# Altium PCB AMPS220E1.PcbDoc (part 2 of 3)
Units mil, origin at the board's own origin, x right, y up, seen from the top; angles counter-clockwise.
Board outline 4800 x 2800 mil, 4 copper layers (Top Layer, GND_Split, GROUND, Bottom Layer), stack 62.6 mil thick; 263 components, 127 nets, 663 pads, 225 vias.
Unrouted connection lines stored in the file: 38.
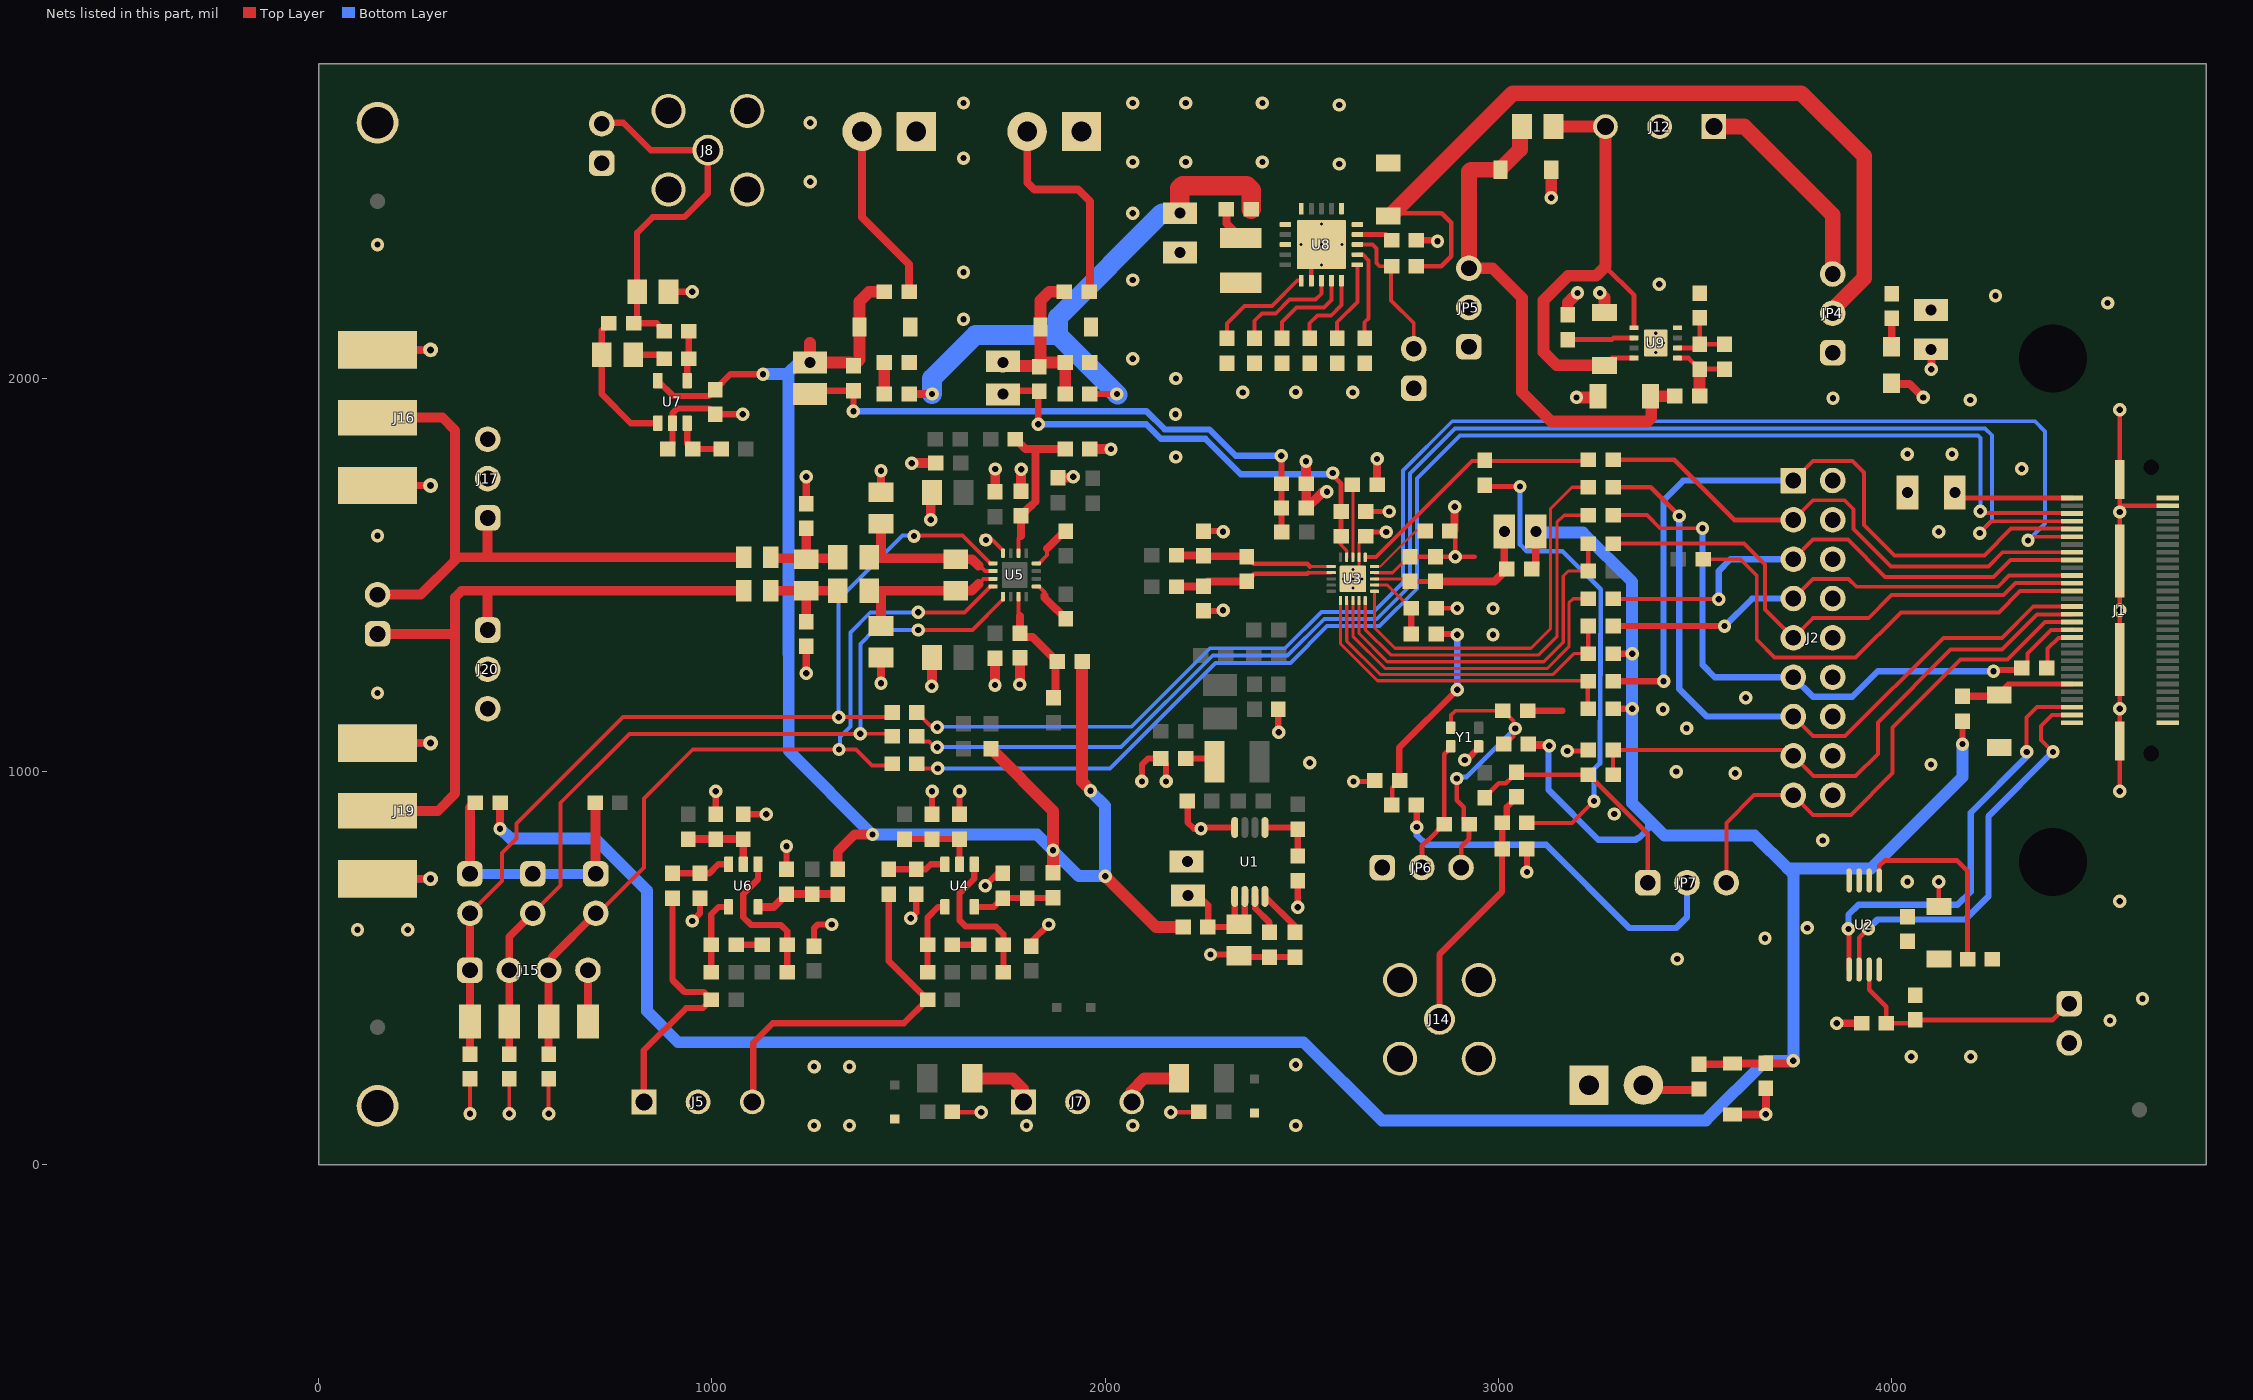
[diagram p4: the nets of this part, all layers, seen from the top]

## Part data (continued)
J3 J4 J6 J18 JP1 JP2: library part CMP-0075405-3, "Header, 100mil, 2x1, Gold, TH", Color=Black, Current_A=6.3A, Manufacturer=Samtec, PartNumber=TSW-102-07-G-S, Supplier Part Number 1=SAM1029-02-ND, Voltage_V=550V
J5 J7 J12: library part CMP-0055340-2, "Terminal Block, 3.5 mm, 3x1, Tin, TH", Manufacturer=Molex, Supplier Part Number 1=WM7878-ND
J8 J14: library part CMP-0055833-1, "SMA Straight Jack, Gold, 50 Ohm, TH", Manufacturer="Amphenol RF", Supplier Part Number 1=ARFX1231-ND
J9: library part CMP-0075405-3, "Header, 100mil, 2x1, Gold, TH", Color=Black, Current_A=6.3A, Manufacturer=Samtec, Supplier Part Number 1=SAM1029-02-ND, Voltage_V=550V
J10 J11 J13: library part CMP-0074913-1, "Terminal Block, 3.5mm Pitch, 2x1, TH", Color=Grey, Current_A=6A, Manufacturer="On-Shore Technology", Supplier Part Number 1=ED1514-ND, Voltage_V=150V
J15: library part CMP-0075409-2, "Header, 100mil, 4x1, Gold, TH", Color=Black, Current_A=6.3A, Manufacturer=Samtec, Supplier Part Number 1=SAM1029-04-ND, Voltage_V=550V
J16 J19: library part CMP-0055828-1, "Connector, End launch SMA, 50 ohm, SMT", Manufacturer="Cinch Connectivity", Supplier Part Number 1=J502-ND
J17 J20 JP4 JP5 JP6 JP7: library part CMP-0075407-2, "Header, 100mil, 3x1, Gold, TH", Color=Black, Current_A=6.3A, Manufacturer=Samtec, Supplier Part Number 1=SAM1029-03-ND, Voltage_V=550V
LBL1: library part CMP-0003625-1, "Thermal Transfer Printable Labels, 0.650\" W x 0.200\" H - 10,000 per roll", Manufacturer=Brady, Supplier Part Number 1=97C5133
Logo1: library part CMP-0074844-1
Logo2: library part CMP-0074769-1
Logo3: library part CMP-0074838-1, "Texas Instrument Corporate Signature"
Logo4: library part CMP-0074847-1, "FCC_disclaimer"
R1 R2 R4 R17 R21 R22 R23 R29 R30 R33 R35 R37 R41 R42 R45 R50 R51 R52 R53 R54 R56 R57 R59 R60 R71 R72 R73 R74 R75 R78 R81 R82 R83 R84 R89 R90 R92 R93 R94 R96 R97 R98 R100 R101 R196 R197: library part CMP-0025885-5, "RES, 0, 5%, 0.1 W, 0603", Manufacturer=Yageo, Power_W=100mW, Supplier Part Number 1=311-0.0GRCT-ND, TempCo="200 ppm/C", Tolerance_%=5%, Value2=0.1W, Value_Code=0000, ValueDisplayed=0
R3 R65 R70 R86: library part CMP-0022746-5, "RES, 10.0 k, 1%, 0.1 W, 0603", Manufacturer=Yageo, Power_W=100mW, Supplier Part Number 1=311-10.0KHRCT-ND, TempCo="100 ppm/C", Tolerance_%=1%, Value2=0.1W, Value_Code=10k0, ValueDisplayed=10.0k
R5: library part CMP-0022726-3, "RES, 0.047, 1%, 0.1 W, AEC-Q200 Grade 1, 0603", Manufacturer=Panasonic, Power_W=100mW, Supplier Part Number 1=P47LJCT-ND, TempCo="200 ppm/C", Tolerance_%=1%, Value2=0.1W, Value_Code=R047, ValueDisplayed=0.047
R6: library part CMP-0023427-3, "RES, 120 k, 0.1%, 0.1 W, 0603", Manufacturer="Susumu Co Ltd", Power_W=100mW, Supplier Part Number 1=RG16P120KBCT-ND, TempCo="25 ppm/C", Tolerance_%=0.1%, Value2=0.1W, Value_Code=120k
R7 R11 R15 R69: library part CMP-0022725-3, "RES, 0.1, 1%, 0.1 W, AEC-Q200 Grade 1, 0603", Manufacturer=Panasonic, Power_W=100mW, Supplier Part Number 1=P100LJCT-ND, TempCo="200 ppm/C", Tolerance_%=1%, Value2=0.1W, Value_Code=R100, ValueDisplayed=0.1
R8 R9 R10 R12 R13 R14 R16 R18 R32 R47 R67 R95 R129 R130: library part CMP-0022004-4, "RES, 10.0, 1%, 0.25 W, AEC-Q200 Grade 0, 0603", Manufacturer=Vishay-Dale, Power_W=250mW, Supplier Part Number 1=541-10.0SCT-ND, TempCo="100 ppm/C", Tolerance_%=1%, Value2=0.25W, Value_Code=10R0, ValueDisplayed=10.0
R19 R20 R68 R91 R198: library part CMP-0021990-4, "RES, 100 k, 1%, 0.1 W, AEC-Q200 Grade 0, 0603", Manufacturer=Vishay-Dale, Power_W=100mW, Supplier Part Number 1=541-100KHCT-ND, TempCo="100 ppm/C", Tolerance_%=1%, Value2=0.1W, Value_Code=100k
R24 R31 R36 R46 R58 R63 R66: library part CMP-0022109-5, "RES, 1.00 k, 1%, 0.1 W, AEC-Q200 Grade 0, 0603", Manufacturer=Vishay-Dale, Power_W=100mW, Supplier Part Number 1=541-1.00KHCT-ND, TempCo="100 ppm/C", Tolerance_%=1%, Value2=0.1W, Value_Code=1k00, ValueDisplayed=1.00k
R25 R34 R49 R55: library part CMP-0021991-4, "RES, 100, 1%, 0.1 W, AEC-Q200 Grade 0, 0603", Manufacturer=Vishay-Dale, Power_W=100mW, Supplier Part Number 1=541-100HCT-ND, TempCo="100 ppm/C", Tolerance_%=1%, Value2=0.1W, Value_Code=100R, ValueDisplayed=100
R26 R27 R28: library part CMP-0023337-3, "RES, 10.0 k, 1%, 0.1 W, 0603", Manufacturer="Vishay Draloric", Power_W=100mW, Supplier Part Number 1=541-1784-1-ND, TempCo="100 ppm/C", Tolerance_%=1%, Value2=0.1W, Value_Code=10k0, ValueDisplayed=10.0k
R38 R44: library part CMP-0024268-3, "RES, 47.5, 0.1%, 0.1 W, 0603", Manufacturer="Yageo America", Power_W=100mW, TempCo="25 ppm/C", Tolerance_%=0.1%, Value2=0.1W, Value_Code=47R5, ValueDisplayed=47.5
R39 R48: library part CMP-0020833-2, "RES, 0, 1%, 0.5 W, 0805", Manufacturer=Keystone, Power_W=500mW, Supplier Part Number 1=36-5106CT-ND, TempCo=ppm/C, Tolerance_%=1%, Value2=0.5W, Value_Code=0
R40 R43: library part CMP-0018851-2, "RES, 100, 0.1%, 0.125 W, 0805", Manufacturer="Susumu Co Ltd", Power_W=125mW, Supplier Part Number 1=RG20P100BCT-ND, TempCo="25 ppm/C", Tolerance_%=0.1%, Value2=0.125W, Value_Code=100R, ValueDisplayed=100
R61 R62: library part CMP-0018402-2, "RES, 5.49, 1%, 0.25 W, 1206", Manufacturer="Yageo America", Power_W=250mW, Supplier Part Number 1=311-5.49FRCT-ND, TempCo="200 ppm/C", Tolerance_%=1%, Value2=0.25W, Value_Code=5R49, ValueDisplayed=5.49
R64: library part CMP-0023063-4, "RES, 37.4, 1%, 0.1 W, 0603", Manufacturer=Yageo, Power_W=100mW, Supplier Part Number 1=311-37.4HRCT-ND, TempCo="100 ppm/C", Tolerance_%=1%, Value2=0.1W, Value_Code=37R4, ValueDisplayed=37.4
R76 R77 R79: library part CMP-0023206-5, "RES, 5.11, 1%, 0.1 W, 0603", Manufacturer=Yageo, Power_W=100mW, Supplier Part Number 1=311-5.11HRCT-ND, TempCo="200 ppm/C", Tolerance_%=1%, Value2=0.1W, Value_Code=5R11, ValueDisplayed=5.11
R80: library part CMP-0022760-5, "RES, 11.3 k, 1%, 0.1 W, 0603", Manufacturer=Yageo, Power_W=100mW, Supplier Part Number 1=311-11.3KHRCT-ND, TempCo="100 ppm/C", Tolerance_%=1%, Value2=0.1W, Value_Code=11k3, ValueDisplayed=11.3k
R85: library part CMP-0020803-2, "RES, 0, 5%, 0.125 W, 0805", Manufacturer="Yageo America", Power_W=125mW, Supplier Part Number 1=311-0.0ARCT-ND, TempCo="200 ppm/C", Tolerance_%=5%, Value2=0.125W, Value_Code=0000, ValueDisplayed=0
R87 R88: library part CMP-0024285-2, "RES, 49.9, 0.1%, 0.1 W, 0603", Manufacturer="Yageo America", Power_W=100mW, TempCo="25 ppm/C", Tolerance_%=0.1%, Value2=0.1W, Value_Code=49R9, ValueDisplayed=49.9
SH-J1 SH-J2 SH-J3 SH-J4 SH-J5 SH-J6 SH-J7 SH-J8 SH-J9: library part CMP-0003642-1, "Shunt, 100mil, Flash Gold, Black", Manufacturer="Sullins Connector Solutions", Supplier Part Number 1=S9001-ND
TP1 TP2 TP3 TP4 TP5 TP6 TP7 TP8 TP9 TP10 TP11 TP12 TP13 TP14 TP15 TP16 TP19 TP20 TP21 TP22: library part CMP-0003968-1, "Test Point, SMT", Manufacturer=Harwin, PartNumber=S2751-46R, Supplier Part Number 1=952-2664-1-ND
TP17 TP18: library part CMP-0055119-1, "Terminal, Turret, TH, Double", Manufacturer=Keystone, PartNumber=1573-2, Supplier Part Number 1=36-1573-2-ND
U1: library part CMP-0077708-1, "High-Precision Voltage Reference with Integrated High-Bandwidth Buffer, DGK0008A (VSSOP-8)", Alternate Manufacturer="Texas Instruments", Alternate PartNumber=REF6225IDGKT
U2: library part CMP-0004843-1, "I2C BUS EEPROM (2-Wire), TSSOP-B8", Manufacturer=Rohm, Supplier Part Number 1=BR24G32FVT-3AG2CT-ND
U3: library part CMP-0097348-1, "512-kSPS, Wide-Bandwidth, 24-Bit, Delta-Sigma ADC", Manufacturer="Texas Instruments", Max Supply Voltage=5.5V, Min Supply Voltage=1.65V, Operating Temperature Range="to +150°C"
U4 U6 U7: library part CMP-0040538-1, "Precision, Rail-to-Rail Input/Output, Low Offset Voltage, Low Input Bias Current Op Amp with E-trim, 4.5 to 36 V, -40 to 125 degC, 5-Pin SOT-23 (DBV), Green (RoHS & no Sb/Br), Tape and Reel", Temperature Max="125 degC", Temperature Min="-40 degC"
U5: library part CMP-0120091-1, "Low-Noise, Wide-Bandwidth, Fully Differential Output Programmable-Gain Instrumentation Amplifier", Input Bias Current=0.0005uA, Input Offset Voltage=0.07mV, Manufacturer="Texas Instruments", Max Dual Supply Voltage=18V, Max Supply Voltage=36V, Min Dual Supply Voltage=4V, Min Supply Voltage=8V, Nominal Supply Current=3mA, Operating Temperature Range="-40°C to +125°C", Output Current Per Channel=45mA, Voltage Gain=0.000125-0.016V/mV
U8: library part CMP-0066918-2, "36-V, 1-A, 4.17-uVRMS, RF LDO Voltage Regulator, RGW0020A (VQFN-20)", Alternate Manufacturer="Texas Instruments", Alternate PartNumber=TPS7A4700RGWT
U9: library part CMP-0073865-3, "Vin -3V to -36V, -200mA, Ultra-Low-Noise, High-PSRR, Low-Dropout (LDO) Linear Regulator, DRB0008A (VSON-8)", Alternate Manufacturer="Texas Instruments", Alternate PartNumber=TPS7A3001DRBT, Operating Temperature Range="-40 to 125 C", Rating=Catalog
Y1: library part CMP-0095447-1, "32.768 MHz XO (Standard) CMOS Oscillator 1.6V ~ 3.63V Standby (Power Down) 4-SMD, No Lead", Digikey Part Number=478-KC2016K32.7680C1GE00CT-ND, Frequency_Fixed=32.768MHz, Load Capacitance=15pF, Manufacturer=Kyocera, Max Supply Current=3.5-5mA, Max Supply Voltage=3.63V, Min Supply Voltage=1.6V, Mouser Part Number=581-KC2016K32.76C1GE, Operating Temperature Range="-40°C to +85°C"
ZZ1: library part CMP-0003616-3
ZZ2: library part CMP-0077236-1
ZZ3: library part CMP-0077237-1
ZZ4: library part CMP-0077238-1

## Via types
v1: diameter 34, hole 16, Top Layer to Bottom Layer, tented both sides, 161 vias
v2: diameter 34, hole 16, Top Layer to Bottom Layer, 30 vias
v3: diameter 50, hole 28, Top Layer to Bottom Layer, 15 vias
v4: diameter 19.68, hole 7.87, Top Layer to Bottom Layer, tented both sides, 10 vias
v5: diameter 19.68, hole 7.87, Top Layer to Bottom Layer, 9 vias

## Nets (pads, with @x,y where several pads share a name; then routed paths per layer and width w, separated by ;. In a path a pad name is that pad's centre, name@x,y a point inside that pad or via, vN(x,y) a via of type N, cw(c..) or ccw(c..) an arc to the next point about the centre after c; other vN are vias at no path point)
5V_LDO: R69.2 R71.2 R74.2 TP14.1 U8.1 U8.3 U8.20 | length 1501
  Top Layer w16: R74.2@1961.5,1960 v1(2030,1960)
  Top Layer w20: R71.2@1501.5,1960 v1@1548.5,1960
  Top Layer w50: v3(2190,2420) 2190,2482.95 2197.05,2490 2359.61,2490 2371.5,2478.11 R69.2@2371.5,2430
  Bottom Layer w50: v1(1560,1960) 1560,1999.47 1670.53,2110 1880,2110 ; v1@2032.05,1957.95 v1(2030,1960) 1880,2110 ; v3(2190,2420) 2145,2420 1880,2155 1880,2110
+Vin: J12.1 JP4.3 | length 535.4
  Top Layer w40: J12.1@3547.8,2640 3625,2640 3850,2415 JP4.3@3850,2275
-2.5V: C52.2 D7.2 JP5.3 R84.1 R85.2 | length 1347.3
  Top Layer w30: JP5.3@2925,2280 2985,2280 3060,2205 3060,1965 3135,1890 3378.84,1890 3388.84,1900 3388.84,1952.5 C52.2@3386.91,1954.42 3448.43,1954.92 R84.1@3448.5,1955
  Top Layer w40: JP5.3@2925,2280 2925,2525.64 2929.68,2530.32 D7.2@3005.53,2530.32 3005.53,2532.35 3055,2581.81 3055,2635 R85.2@3060,2640
-Vin: C56.2 J12.3 R85.1 U9.5 U9.8 | length 1250.3
  Top Layer w12: C56.2@3270,2033.07 3288.54,2051.61 U9.8@3344.88,2051.61 ; 3272.2,2283.94 3344.88,2211.26 U9.5@3344.88,2128.39
  Top Layer w30: R85.1@3140,2640 J12.3@3272.2,2640 3272.2,2283.94 3248.99,2260.72 3177.06,2260.72 3115,2198.66 3115,2066.08 3148.01,2033.07 C56.2@3270,2033.07
A0: J6.2 J15.3 R28.2 R32.1 TP21.1 U5.4 | length 2165
  Top Layer w10: J6.2@705,640 711.45,640 827.2,755.75 827.2,931.87 951.5,1056.16 v2(1323.42,1056.16) 1366.23,1056.16 1406.79,1015.59 1454.09,1015.59 R32.1@1458.5,1020 ; v2(1525,1405) 1642.68,1405 1708.15,1470.47 U5.4@1714.88,1470.47
  Top Layer w20: R28.2@585,281.5 TP21.1@585,360 ; TP21.1@585,371.5 J15.3@585,495 593.6,503.6 593.6,528.6 J6.2@705,640
  Bottom Layer w10: v2(1323.42,1056.16) 1325.91,1058.66 1325.91,1088.16 1352.29,1114.54 1352.29,1354.21 1402.75,1404.67 v2(1525,1405)
A1: J4.2 J15.2 R27.2 R47.1 TP20.1 U5.5 | length 2245.6
  Top Layer w10: J4.2@545,640 615,710 615,920.71 790.32,1096.03 1377.37,1096.03 v2(1377.49,1096.16) 1452.34,1096.16 R47.1@1458.5,1090 ; v2(1525,1360) 1662.32,1360 1740.47,1438.15 U5.5@1740.47,1444.88
  Top Layer w20: R27.2@485,281.5 TP20.1@485,360 ; TP20.1@485,371.5 J15.2@485,495 485,580 J4.2@545,640
  Bottom Layer w10: v2(1377.49,1096.16) 1377.49,1324.78 1412.71,1360 v2(1525,1360)
A2: J3.2 J15.1 R26.2 R67.1 TP19.1 U5.1 | length 2484.6
  Top Layer w10: J3.2@385,640 466.3,721.3 466.3,792.68 503.7,830.08 503.7,867.76 774.43,1138.49 v2(1322.42,1138.49) 1446.99,1138.49 R67.1@1458.5,1150 ; v2(1514,1598.82) 1515.18,1600 1637.68,1600 1708.15,1529.53 U5.1@1714.88,1529.53
  Top Layer w20: R26.2@385,281.5 TP19.1@385,360 ; TP19.1@385,371.5 J15.1@385,495 J3.2@385,640
  Bottom Layer w10: v2(1322.42,1138.49) 1322.42,1437.42 1485,1600 1505.72,1600 1506.9,1598.82 v2(1514,1598.82)
ADC.C\S\: J1.22 J2.7 R13.2 | length 1236.9
  Top Layer w10: J2.7@3750,1440 3800,1490 3890,1490 3910,1470 4270,1470 4298.7,1498.7 J1.22@4458.5,1498.7
  Top Layer w16: R13.2@3291.5,1370 v1(3575,1370)
  Bottom Layer w16: v1(3575,1370) 3645,1440 J2.7@3750,1440
ADC.D\R\D\Y\: J1.30 J2.13 R14.2 | length 1823.6
  Top Layer w10: J2.13@3750,1140 3800,1090 3881.32,1090 4131.32,1340 4280,1340 4359.9,1419.9 J1.30@4458.5,1419.9
  Top Layer w12: R14.2@3291.5,1723.04 3386.96,1723.04 v1(3460,1650)
  Bottom Layer w16: v1(3460,1650) 3460,1210 3530,1140 J2.13@3750,1140
ADC.MCLK_IN: C58.2 J1.32 J2.15 R87.2 | length 1474.7
  Top Layer w10: R87.2@3291.5,992.31 C58.2@3291.5,1055 3735,1055 J2.15@3750,1040 3801.61,988.39 3908.39,988.39 3965,1045 3965,1125 4150,1310 4280,1310 4369.2,1399.2 4457.5,1399.2 J1.32@4458.5,1400.2
ADC.MCLK_OUT: J1.34 J2.17 JP7.3 | length 1352.3
  Top Layer w10: JP7.3@3579.49,717.4 3579.49,869.74 3649.74,940 J2.17@3750,940 3800,890 3896.09,890 4002.44,996.35 4002.44,1112.44 4175.2,1285.2 4294.84,1285.2 4390.14,1380.5 J1.34@4458.5,1380.5
ADC.R\E\S\E\T\: J1.10 J2.1 R18.2 | length 1894
  Top Layer w10: J2.1@3750,1740 3800,1790 3900,1790 3930,1760 3930,1627.2 4007.2,1550 4236.02,1550 4303.71,1617.69 4450.46,1617.69 4451.25,1616.9 J1.10@4458.5,1616.9
  Top Layer w12: J2.1@3750,1740 J2.1@3770,1740
  Top Layer w16: R18.2@3291.5,1230 v1(3420,1230)
  Bottom Layer w16: v1(3420,1230) 3420,1690 3470,1740 J2.1@3750,1740
ADC.SCLK: J1.24 J2.9 R9.2 | length 1391.5
  Top Layer w10: R9.2@3291.5,1579.57 3291.93,1580 3625,1580 3677.95,1527.05 3677.95,1412.05 J2.9@3750,1340 3800,1390 3941.5,1390 4000,1448.5 4283.81,1448.5 4314.31,1479 J1.24@4458.5,1479
ADC.SDI: J1.18 J2.5 R10.2 | length 1329.3
  Top Layer w10: R10.2@3291.5,1439.6 3292.59,1438.5 v1(3560,1438.5) ; J2.5@3750,1540 3800,1590 3888.5,1590 3983.5,1495 4258.5,1495 4301.6,1538.1 J1.18@4458.5,1538.1
  Bottom Layer w16: v1(3560,1438.5) 3560,1510 3590,1540 J2.5@3750,1540
ADC.SDO/D\R\D\Y\: J1.36 J2.11 R12.2 R96.1 | length 1651.5
  Top Layer w10: R12.2@3291.5,1651.9 3378.15,1651.9 3411.3,1618.75 v1@3506.65,1618.75 ; v1@3518.9,1606.5 v1@3506.65,1618.75 ; v1(3518.9,1618.75) v1@3506.65,1618.75 ; R96.1@4330.94,1263.33 4331.93,1263.33 4345.63,1277.03 4345.63,1300.69 4404.74,1359.8 4457.5,1359.8 J1.36@4458.5,1360.8
  Top Layer w16: v1(4258.75,1255) 4262.19,1258.44 4326.06,1258.44 R96.1@4330.94,1263.33
  Bottom Layer w16: v1@3518.9,1606.5 3518.9,1271.45 3550.36,1240 J2.11@3750,1240 3800,1190 3900,1190 3965,1255 v1(4258.75,1255)
ADC.START/SYNC: J1.16 J2.3 R16.2 | length 1365.2
  Top Layer w10: J2.3@3750,1640 3800,1690 3880,1690 3902.98,1667.02 3902.98,1617.02 3998.5,1521.5 4245.95,1521.5 4282.25,1557.8 J1.16@4458.5,1557.8
  Top Layer w12: R16.2@3291.5,1792.95 3447.05,1792.95 3600,1640 J2.3@3750,1640
AINN: C62.2 C65.2 R44.2 U3.2 | length 409.3
  Top Layer w8: 2516.81,1505.75 U3.2@2574.88,1505.75
  Top Layer w12: C62.2@2360,1483.5 2360,1484.49 2372.7,1497.19 2373.69,1497.19 2379.29,1502.8 2513.86,1502.8 2516.81,1505.75
  Top Layer w20: R44.2@2181.5,1470 2182.24,1470.75 2249.25,1470.75 C65.2@2250,1471.5 2250,1472.48 2258.7,1481.18 2259.69,1481.18 2262.01,1483.5 C62.2@2360,1483.5
AINP: C36.1 C62.1 R38.2 U3.1 | length 405.8
  Top Layer w8: 2520.75,1521.5 U3.1@2574.88,1521.5
  Top Layer w12: C62.1@2360,1546.5 2360,1545.51 2372.7,1532.81 2373.69,1532.81 2378.11,1528.39 2513.86,1528.39 2520.75,1521.5
  Top Layer w20: R38.2@2181.5,1550 2182.24,1549.25 2249.25,1549.25 C36.1@2250,1548.5 2251,1547.5 2359,1547.5 C62.1@2360,1546.5
AVDD1: C46.2 C54.2 D5.1 R1.1 R7.2 R17.2 R29.1 R50.1 R51.1 R71.1 R76.1 TP7.1 U7.5 | length 4177.8
  Top Layer w16: U7.5@862.6,1994.13 901.73,1955 992.34,1955 C46.2@1008.84,1971.5 1047.34,2010 v1(1130,2010)
  Top Layer w25: R51.1@1320,751.5 1320,796.73 1363.27,840 v1(1408.43,840)
  Top Layer w30: 1250,2090 v3(1250,2040) 1351.5,2040 R7.2@1360,2031.5 1375.53,2047.03 D5.1@1375.53,2130 1375.53,2195.53 1400,2220 R76.1@1438.5,2220 ; R71.1@1438.5,1960 C54.2@1438.5,2040 ; R17.2@1710,1058.5 1710,1057.52 1867.43,900.09 v1(1867.43,800) R29.1@1867.43,742.64 ; R50.1@1941.5,1280 1941.5,974.04 1962.84,952.69 v2(1962.84,951.61) ; v1(2000,734.24) 2129.24,605 R1.1@2198.5,605
  Bottom Layer w30: v1(1130,2010) 1130.77,2010.77 1191.3,2010.77 1194.87,2014.34 ; 1194.87,1299.19 1194.87,2014.34 ; 1195.55,1298.52 1195.55,1052.87 v1(1408.43,840) 1827.43,840 v1(1867.43,800) 1933.19,734.24 v1(2000,734.24) 2000,913.37 1962.84,950.53 v2(1962.84,951.61) ; v3(1250,2040) 1220.53,2040 1194.87,2014.34
AVDD2: C53.2 D4.1 R11.2 R74.1 R79.1 TP9.1 | length 478.4
  Top Layer w30: v3(1740,2040) 1748.5,2031.5 1830,2031.5 R11.2@1835.53,2037.03 ; R74.1@1898.5,1960 C53.2@1898.5,2040 1838.5,2040 R11.2@1835.53,2037.03 ; R79.1@1898.5,2220 1857.88,2220 1835.53,2197.66 1835.53,2130 R11.2@1835.53,2037.03
AVSS: C2.2 C5.2 C6.1 C7.2 C8.1 C9.2 C11.1 C18.2 C20.2 C21.1 C23.2 C24.2 C25.1 C26.2 C27.1 C28.2 C30.2 C33.2 C34.2 C36.2 C37.1 C39.2 C40.1 C41.1 C44.2 C45.2 C46.1 C48.1 C49.2 C50.1 C53.1 C54.1 C63.1 C64.1 C65.1 C67.1 D4.2 D5.2 J10.1 J11.1 J17.2 J17.3 J20.2 J20.3 JP2.1 JP5.2 R4.1 R5.1 R6.1 R33.2 R41.1 R57.2 R59.1 R72.2 R73.2 R75.2 R78.2 R82.2 R83.2 R89.1 R92.1 TP3.1 TP13.1 U1.8 U3.17 U3.21 U7.2 U8.7 U8.21@2550,2340 | length 3294
  Top Layer w8: U3.21@2645.75,1513.62 U3.17@2645.75,1545.12 2645.75,1582.36 C8.1@2661.9,1598.5
  Top Layer w10: v4(2606.38,1490) v4(2630,1490) ; v4(2630,1466.38) v4(2630,1490) ; v4(2630,1513.62) v4(2630,1490) ; v4(2653.62,1490) v4(2630,1490)
  Top Layer w12: U8.7@2524.41,2248.46 2524.41,2314.41 v5(2550,2340) ; C8.1@2661.9,1598.5 2672.72,1609.33 v1(2715.19,1609.33) ; C9.2@2662.88,1661.5 C9.2@2662.88,1661.5 v1(2722.72,1661.46)
  Top Layer w16: C44.2@888.5,1820 900,1831.5 U7.2@900,1885.87 900,1911.5 911.5,1923 994.34,1923 C46.1@1008.84,1908.5 v1(1078.5,1908.5) ; C45.2@890,2220 v1(950,2220) v1@953.36,2220 ; v1(950,620) 970,640 C40.1@970,678.5 ; R59.1@1010,891.5 v1(1010,950) ; C41.1@1080,891.5 v1(1138.5,891.5) ; C37.1@1190,751.5 v1(1190,810) ; v1@1237.42,1742.39 v1@1237.58,1742.55 ; C39.2@1260,556.5 1260,602.26 1268.89,611.15 v1(1305,611.15) ; v1(1505.72,626.87) 1520,641.15 C25.1@1520,688.5 ; R41.1@1560,891.5 v1(1560,950) ; C27.1@1630,891.5 v1@1630,940 ; v1(1695.44,710) 1726.93,741.5 C21.1@1740,741.5 ; C24.2@1813.62,556.5 1813.62,568.35 v1(1856.41,611.15) ; v1(2093.58,975) 2093.58,1017.8 2108.85,1033.06 R5.1@2142.05,1033.06 2155,1020.1 v1(2155,975) ; R92.1@2208.5,925 2210.34,923.17 2210.34,870.39 2226.18,854.55 v1(2243.8,854.55) 2247.08,857.84 U1.8@2329.57,857.84 ; C65.1@2250,1408.5 v1@2298.5,1408.5 ; C36.2@2250,1611.5 2298.5,1611.5 v1(2300,1610) ; v1(2267.95,535) 2340.53,535 2347.03,528.5 R6.1@2417.95,528.5 C5.2@2482.95,528.5 ; R4.1@2440,1158.5 2440,1101.61 v1(2441.61,1100) ; v1(2490,655) R89.1@2490,722.4 ; C50.1@2791.5,2351.38 2842.43,2351.38 v1(2845,2348.81)
  Top Layer w20: v1(1240,1250) C63.1@1240,1318.5 ; C33.2@1240,1681.5 v1(1240,1750) ; v1(1430,1225) C64.1@1430,1293.5 ; C34.2@1430,1710 v2(1430,1765) ; C11.1@2691.5,1729.26 v1(2691.5,1795)
  Top Layer w25: v2(1508.2,1784.25) R33.2@1569.63,1784.71 ; v2@1517.2,1784.25 v2@1517.66,1784.71 ; v2(1556.73,1640.05) 1556.73,1706.73 C26.2@1560,1710 ; v2@1556.73,1647.05 1556.69,1647.09 1556.69,1649.96 v2@1556.73,1650 ; v2(1559.13,1216.74) 1560,1217.61 C20.2@1560,1290 ; v2(1720,1220) C18.2@1720,1288.5 ; C23.2@1720,1711.5 1720.79,1712.28 v2(1720.79,1769.27) ; v2(1783.3,1221.5) 1783.46,1221.65 C28.2@1783.46,1288.98 ; C67.1@1786.14,1712.99 1786.14,1768.51 v2(1786.46,1768.83) ; C30.2@1880,1747 1916.2,1747 v2(1918.7,1749.5) ; R57.2@1961.5,1820 v2@2017.43,1820 ; v1@2510.65,1774.25 2510.65,1720.84 2511.5,1720 C7.2@2511.5,1670 2512.48,1670 2552.25,1709.77 2562.21,1709.77 v1(2563.93,1711.5)
  other v1: 1630,950 2520,1022.42 2300,1410 2510.65,1789.25 2180,1800 2178.82,1908.7 2350,1964.11 2630,1964.11 2485,1965 2180,1999.47 2070,2050 1640,2150 2070,2250 1640,2270 2070,2420 1250,2500 2595,2545 2070,2550 2205,2550 2400,2550 1640,2560 1250,2650 2595,2695 1640,2700 2070,2700 2205,2700 2400,2700
  other v2: 2015,1820
  other v3: 2209.43,771.5 2190,2320
  other v5: 2550,2287.83 2497.83,2340 2602.17,2340 2550,2392.17
CAP_SCLK: J1.26 R95.2 | length 1206.9
  Top Layer w10: R95.2@3520.85,1540 3615.66,1540 3656.96,1498.7 3656.96,1335.48 3702.43,1290 3908.24,1290 4023.24,1405 4272.46,1405 4326.76,1459.3 J1.26@4458.5,1459.3
CLK: C59.2 R88.2 U3.12 | length 182.9
  Top Layer w8: U3.12@2685.12,1474.25 2718.15,1474.25 2777.4,1415 C59.2@2778.39,1415
  Top Layer w16: C59.2@2778.39,1415 2778.39,1350.14 R88.2@2778.52,1350
eCLK: R129.2 R130.2 | length 1224.2
  Top Layer w10: R129.2@3072.53,869.66 3187.63,869.66 v1(3243.03,925.06)
  Top Layer w12: R130.2@2965,1728.5 2968.5,1725 v1@3049.89,1725
  Bottom Layer w12: v1(3054.89,1725) 3054.89,1577.6 3072.1,1560.39 3162.99,1560.39 3260,1463.38 3258.26,1020.86 3243.03,1005.63 v1(3243.03,925.06)
EVM_5V: J1.2 TP6.1 | length 304
  Top Layer w12: v3(4160.44,1710) 4174.74,1695.7 J1.2@4458.5,1695.7
EVM_DVDD: C14.1 J1.50 R81.2 | length 292.8
  Top Layer w12: C14.1@4270,1196.93 4295.97,1222.9 J1.50@4458.5,1222.9
  Top Layer w20: R81.2@4180,1191.5 4261.5,1191.5 C14.1@4270,1200
EVM_ID_PWR: C1.2 C17.2 R3.1 R21.2 U2.1 U2.8 | length 502.3
  Top Layer w12: U2.1@3968.39,723.19 3968.39,760.23 3982,773.85 4166.15,773.85 4192.8,747.2 R21.2@4192.8,523.07
EVM_ID_SCL: J1.58 U2.6 | length 1057.4
  Top Layer w10: v1(4410,1050) 4380,1080 4380,1116.43 4407.67,1144.1 J1.58@4458.5,1144.1
  Top Layer w12: U2.6@3917.2,496.81 3917.2,577.2 v1(3940,600)
  Bottom Layer w10: v1@3940,599.67 v1(3940,600)
  Bottom Layer w16: v1(3940,600) 3963.88,623.88 4187.44,623.88 4245.95,682.38 4245.95,885.95 v1(4410,1050)
EVM_ID_SDA: J1.56 U2.5 | length 1102.9
  Top Layer w10: v1(3890,600) v1@3891.61,598.39 ; v1(4343.3,1050) 4343.3,1137.9 4369.2,1163.8 J1.56@4458.5,1163.8
  Top Layer w12: U2.5@3891.61,496.81 v1@3891.61,598.39
  Bottom Layer w16: v1(3890,600) 3890,635.65 3915.53,661.18 4167.33,661.18 4200.68,694.53 4200.68,895.68 4343.3,1038.3 v1(4343.3,1050)
EVM_REG_5V5: J1.1 JP4.1 R70.2 TP15.1
  other v3: 4100,2173.66
FDA_INN: C66.2 U5.9 | length 116.3
  Top Layer w10: U5.9@1825.12,1470.47 1831.85,1470.47 1846,1456.32 1846,1447.51
  Top Layer w20: 1846,1447.51 1846,1442.08 1875.75,1412.33 ; 1877.16,1412.33 1900,1389.49 C66.2@1900,1388.5
FDA_INP: C32.2 U5.12 | length 120.9
  Top Layer w10: U5.12@1825.12,1529.53 1831.85,1529.53 1852.44,1550.11 1852.44,1566.89 ; C32.2@1900,1610.51 C32.2@1900,1611.5
  Top Layer w20: 1852.44,1566.89 C32.2@1900,1614.45
GND: C1.1 C4.2 C10.1 C12.1 C13.2 C14.2 C17.1 C42.1 C43.1 C51.1 C52.1 C55.2 C56.1 C57.2 C58.1 C59.1 C127.1 D1.2 D2.1 D3.2 D6.2 D7.1 J1.3 J1.60 J1.MP1 J1.MP2 J1.MP3 J1.MP4 J2.2 J2.4 J2.6 J2.8 J2.10 J2.12 J2.14 J2.16 J2.18 J5.2 J7.2 J8.2 J8.3 J8.4 J8.5 J9.1 J12.2 J13.1 J14.2 J14.3 J14.4 J14.5 J15.4 J16.2 J16.3 J16.4 J16.5 J19.2 J19.3 J19.4 J19.5 JP1.2 JP5.1 JP6.1 R26.1 R27.1 R28.1 R86.1 R198.2 TP5.1 TP16.1 TP17.1 TP18.1 TP22.1 U2.2 U2.3 U2.4 U3.14 U5.16 U9.4 U9.9 Y1.2 | length 3147.7
  Top Layer w8: U3.14@2685.12,1505.75 2730.6,1505.75 2771.35,1546.5 C13.2@2778.17,1546.5
  Top Layer w10: v2(385,130) R26.1@385,218.5 ; v2(485,130) R27.1@485,218.5 ; v2(585,130) R28.1@585,218.5 ; J15.4@685,490 J15.4@685,495 ; v2@1686.93,1598.84 1703.48,1598.84 1740.47,1561.85 U5.16@1740.47,1555.12
  Top Layer w12: C42.1@1610.32,133.82 C42.1@1611.5,135 1612.68,133.82 v1@1671.5,133.82 ; v1(2166.82,133.94) 2237.44,133.94 C43.1@2238.5,135 C43.1@2239.57,133.94 ; v1(2631.62,974.75) 2683.52,974.75 C127.1@2686.16,977.39 ; C13.2@2778.17,1546.5 C12.1@2840,1546.5 v1(2890,1546.5) ; C59.1@2841.38,1415 v1(2895,1415) ; C10.1@2886.5,1611.5 2890,1607.99 v1(2890,1546.5) ; 2940,1546.5 v1(2890,1546.5) ; v1(3175,1052.31) 3225.82,1052.31 C58.1@3228.5,1055 ; C17.1@4120,656.93 v1(4120,720) ; v1(4580,950) J1.MP4@4580,1077.7 v1(4580,1160) J1.MP3@4580,1285.2 v1(4580,1410) J1.MP2@4580,1535.2 v1(4580,1660) v1@4580,1676 ; v1(4580,1920) J1.MP1@4580,1742.7 v1@4580,1676 ; J1.3@4701.5,1676 v1@4580,1676
  Top Layer w16: v1(2631.62,974.75) v1@2631.62,979.62 ; v1(2914.65,1029.57) 2919.15,1029.57 2949.71,1060.13 Y1.2@2949.71,1064.07 ; v1(3072.53,744.58) R198.2@3072.53,803.42 ; C55.2@3074.41,1154.7 3074.5,1154.61 3162.99,1154.61
  Top Layer w20: TP22.1@685,360 J15.4@685,490 ; C10.1@2886.5,1611.5 2888.67,1613.67 v1(2888.67,1673.5) ; D6.2@3595,128.5 v1(3680,128.5) C51.1@3680,195.04 ; v1(3860,360) C4.2@3923.27,360 ; D3.2@4000,1987.4 4001.7,1985.7 4045.68,1985.7 v1(4080,1951.38) ; v3(4100,2073.66) 4100.78,2072.88 v1(4100.78,2022.86)
  Top Layer w30: v1(3134.47,2459.24) D7.1@3134.47,2530.32 ; C57.2@3176.57,2161.5 3176.57,2192.5 v1(3201.18,2217.11) ; v1(3198.5,1951.38) 3254.53,1951.38 C52.1@3253.05,1954.42 ; v1(3258.07,2217.11) 3270,2205.18 C56.1@3270,2166.93
  other v1: 1260,100 1350,100 1800,100 2070,100 2485,100 1685.11,133.82 1260,250 1350,250 2485,254.75 4050,275 4200.68,275 4555,367.17 4637.55,422.62 3454.86,523.5 3677.95,575.94 99,598.18 226.56,598.18 3785,602.52 4580,670 4040,720 3825,825 3294.4,892.17 3602.49,995.56 3452.49,1000 4100,1018.05 3478.45,1110 3418.25,1158.5 3628.8,1187.44 150,1200 2986.38,1348.18 2986.38,1414.66 150,1600 4120,1610 4331.04,1770 4040,1807.33 4153.31,1807.33 4200,1945 3850.69,1949.42 4548.97,2191.5 4263.88,2210.16 3408.84,2238.86 150,2340
  other v2: 1696.93,1588.84
  other v3: 4040,1710
  other v5: 3400,2065.39 3380.32,2090 3419.69,2090 3400,2114.61
INN: C61.2 C64.2 R43.2 U5.3 | length 423.2
  Top Layer w10: 1678.11,1477.2 1690.99,1490.08 1714.8,1490.08 U5.3@1714.88,1490.16
  Top Layer w25: R43.2@1391.5,1460 C61.2@1620,1460 1660.91,1460 1678.11,1477.2 ; C64.2@1430,1373.31 1430,1458.54 1431.46,1460
INN_ext: J16.1 J17.1 J18.2 R39.1 | length 1644
  Top Layer w25: J16.1@120,1900 315,1900 347.14,1867.86 347.14,1537.14 ; J18.2@150,1450 260,1450 347.14,1537.14 ; J17.1@430,1645 430,1545 ; R39.1@1083.5,1545 430,1545 ; 347.14,1537.14 355,1545 430,1545
INP: C34.1 C61.1 R40.2 U5.2 | length 413.2
  Top Layer w10: 1679.45,1525.02 1694.54,1509.92 1714.8,1509.92 U5.2@1714.88,1509.84
  Top Layer w25: R40.2@1391.5,1545 1394,1542.5 1475,1542.5 1617.5,1542.5 C61.1@1620,1540 1661.79,1540 1678.11,1523.68 ; 1430,1542.5 C34.1@1430,1618.5
INP_ext: J18.1 J19.1 J20.1 R48.1 | length 1755.5
  Top Layer w25: J19.1@150,900 303.43,900 347.14,943.71 347.14,1350 ; J18.1@150,1350 347.14,1350 ; 363.63,1459.63 347.14,1443.14 347.14,1350 ; 363.63,1460 430,1460 ; J20.1@430,1360 430,1460 ; R48.1@1083.13,1459.63 1083.5,1460 430,1460
IOVDD: C51.2 D6.1 R15.2 R19.2 R20.2 R77.2 R81.1 R98.1 R196.2 TP11.1 | length 7363.5
  Top Layer w10: D6.1@3595,257.44 D6.1@3598.52,255.96
  Top Layer w16: R19.2@3291.5,1160 v1(3340,1160) ; R20.2@3291.5,1300 v1(3340,1300) ; v1(4180,1070) R81.1@4180,1128.5
  Top Layer w20: v2(461.5,855.02) R98.1@461.5,920.71 ; R196.2@3076.5,1070 3078.52,1067.98 3127.54,1067.98 v1(3129.55,1065.96) ; R15.2@3084.8,1515 3095,1525.2 v3(3095,1610) ; R77.2@3510,255.96 D6.1@3598.52,255.96 ; D6.1@3595,257.44 3679.41,257.44 C51.2@3680,258.03 3743.16,258.03 v1(3750,264.87)
  Bottom Layer w16: v1(3129.55,1065.96) 3127.54,1063.94 3127.54,953.11 3253.84,826.8 3349.84,826.8 3354.33,831.29 3357.65,831.29 3381.32,854.97 3381.32,878.68
  Bottom Layer w30: v2(461.5,855.02) 462.58,855.02 487.6,830 702.8,830 835.5,697.3 835.5,390.5 914,312 2504.44,312 2703.44,113 3527.61,113 3679.48,264.87 v1(3750,264.87) 3750,739.26 3735.36,753.89 ; v3(3095,1610) 3097.26,1607.74 3214.8,1607.74 3340,1482.54 v1(3340,1300) v1(3340,1160) 3340,920 3381.32,878.68 3422.65,837.35 3651.9,837.35 3735.36,753.89 ; v1(4180,1070) 4180,986.1 3947.8,753.89 3735.36,753.89
LVDD: C28.1 R50.2 R53.2 U5.7 | length 314.9
  Top Layer w10: U5.7@1779.84,1444.88 1779.84,1399.22 1783.46,1395.61
  Top Layer w20: 1783.46,1395.61 C28.1@1783.46,1351.97 1783.46,1350.98 1792.16,1342.28 1815.24,1342.28 1877.52,1280 1873.74,1276.22 1873.74,1192.26 R53.2@1868.98,1187.5
LVSS: C67.2 R54.1 R57.1 U5.14 | length 420.5
  Top Layer w10: U5.14@1779.84,1555.12 1779.84,1593.07 1786.14,1599.37
  Top Layer w20: R54.1@1771.72,1845 1772.71,1845 1797.71,1820 1822.54,1820 ; 1786.14,1599.37 C67.2@1786.14,1650 1786.14,1650.98 1808.98,1673.83 1810.39,1673.83 1822.54,1685.98 1822.54,1820 ; R57.1@1898.5,1820 1822.54,1820
NetC2_1: C2.1 R1.2 TP4.1 U1.1 U1.2 | length 354.6
  Top Layer w16: v3(2210.34,685) 2237.01,685 2262.01,660 2262.01,605.51 R1.2@2261.5,605 C2.1@2333.79,605 ; U1.1@2329.57,682.64 2329.57,609.22 C2.1@2333.79,605 ; U1.2@2355.16,682.64 2355.16,629.62 C2.1@2340.53,611.74 C2.1@2333.79,605
NetC3_2: C3.2 R5.2 | length 76.2
  Top Layer w16: R5.2@2205.04,1033.06 2269.86,1033.06 C3.2@2277.91,1025
NetC4_1: C4.1 JP1.1 R3.2 U2.7 | length 640.6
  Top Layer w12: U2.7@3942.8,496.81 3942.8,445.7 3986.26,402.23 C4.1@3986.26,360 4051.5,360 R3.2@4060,368.5 4409.8,368.5 JP1.1@4451.29,410
NetC5_1: C5.1 U1.4 | length 122.9
  Top Layer w16: U1.4@2406.34,682.64 2482.95,606.03 C5.1@2482.95,591.5
NetC6_2: C6.2 C7.1 R7.1 R94.1 TP8.1 | length 1501.9
  Top Layer w16: TP8.1@1250,1957 1261.5,1968.5 R7.1@1360,1968.5 v1(1360,1916) v1@1360,1910 ; v1(2447.66,1802.8) 2448.5,1801.96 C6.2@2448.5,1732 2448.5,1609.99 R94.1@2449.17,1609.33
  Bottom Layer w16: v1(1360,1916) 2105.34,1916 2151.35,1870 2264.93,1870 2332.12,1802.8 v1(2447.66,1802.8)
NetC8_2: C8.2 C9.1 R11.1 TP10.1 U3.19 | length 1210.3
  Top Layer w8: C8.2@2600,1579.8 2600,1575.56 2614.26,1561.3 U3.19@2614.25,1545.12
  Top Layer w12: v1(2578.56,1759.34) 2578.56,1753.38 2599.89,1732.06 C9.1@2599.89,1661.5 C8.2@2599.89,1598.5 2600,1598.39 C8.2@2600,1579.8
  Top Layer w16: v3(1740,1960) 1748.5,1968.5 1830,1968.5 v1(1830,1883)
  Bottom Layer w16: v1(1830,1883) 2104.58,1883 2141.46,1846.12 2255.04,1846.12 2344.78,1756.38 2415,1756.38 2575.6,1756.38 v1(2578.56,1759.34)
NetC10_2: C10.2 U3.15 | length 167.6
  Top Layer w6: U3.15@2685.12,1521.5 2699.39,1521.5 2791.73,1613.84 2811.16,1613.84 C10.2@2813.5,1611.5
NetC11_2: C11.2 U3.18 | length 184.8
  Top Layer w8: C11.2@2628.51,1729.26 2630,1727.77 U3.18@2630,1545.12
NetC12_2: C12.2 C13.1 R15.1 TP12.1 U3.13 | length 450.3
  Top Layer w8: U3.13@2685.12,1490 2778.5,1490 C13.1@2785,1483.5
  Top Layer w12: C13.1@2785,1483.5 C12.2@2840,1483.5
  Top Layer w20: C12.2@2840,1483.5 2990.32,1483.5 R15.1@3021.81,1515 3015,1521.81 v3(3015,1610)
NetC19_1: C19.1 R34.1 U4.1 | length 380.4
  Top Layer w16: U4.1@1667.4,764.13 1667.4,727.72 1630,690.31 1630,621.5 1645.45,606.04 1721.66,606.04 1741.5,586.2 C19.1@1741.5,560 R34.1@1741.5,490
NetC19_2: C19.2 R25.2 | length 67
  Top Layer w16: R25.2@1611.5,560 C19.2@1678.5,560
NetC21_2: C21.2 R29.2 R30.1 U4.5 | length 209.9
  Top Layer w16: U4.5@1667.4,655.87 1717.36,655.87 C21.2@1740,678.5 R30.1@1802,678.5 1866.29,678.5 R29.2@1867.43,679.65
NetC25_2: C25.2 R36.1 U4.3 | length 147.8
  Top Layer w16: R36.1@1450,751.5 C25.2@1520,751.5 1544.09,751.5 1556.73,764.13 U4.3@1592.6,764.13
NetC27_2: C27.2 R41.2 R42.1 U4.2 | length 204.4
  Top Layer w16: R42.1@1490,828.5 R41.2@1560,828.5 C27.2@1630,828.5 U4.2@1630,764.13
NetC33_1: C33.1 C60.1 R39.2 R40.1 | length 264.7
  Top Layer w25: R39.2@1146.5,1545 1149,1542.5 1237.5,1542.5 C60.1@1240,1540 ; C33.1@1240,1618.5 C60.1@1240,1540 ; R40.1@1328.5,1545 1326,1542.5 1242.5,1542.5 C60.1@1240,1540
NetC35_1: C35.1 R55.1 U6.1 | length 380.1
  Top Layer w16: U6.1@1117.4,764.13 1117.4,725.91 1080,688.5 1080,630 1100,610 1175.67,610 1191.5,594.17 C35.1@1191.5,560 R55.1@1191.5,490
NetC35_2: C35.2 R49.2 | length 67
  Top Layer w16: R49.2@1061.5,560 C35.2@1128.5,560
NetC37_2: C37.2 R51.2 R52.1 U6.5 | length 216.1
  Top Layer w20: U6.5@1117.4,655.87 1157.36,655.87 C37.2@1190,688.5 R52.1@1255.59,688.5 R51.2@1320,688.5
NetC38_1: C38.1 R80.2 R84.2 U9.1 | length 200
  Top Layer w12: U9.1@3455.12,2051.61 3483.16,2051.61 3511.5,2023.28 R80.2@3511.72,2023.5 C38.1@3575,2023.5
  Top Layer w30: R84.2@3511.5,1955 R80.2@3511.5,2023.28
NetC38_2: C38.2 R80.1 R86.2 U9.2 | length 190.7
  Top Layer w12: U9.2@3455.12,2077.2 3502.43,2077.2 R80.1@3511.72,2086.5 ; R86.2@3511.72,2153.5 R80.1@3511.72,2086.5 ; C38.2@3575,2086.5 R80.1@3511.72,2086.5
NetC40_2: C40.2 R58.1 U6.3 | length 152
  Top Layer w16: R58.1@900,741.5 C40.2@970,741.5 994.09,741.5 1016.73,764.13 U6.3@1042.6,764.13
NetC41_2: C41.2 R59.2 R60.1 U6.2 | length 204.4
  Top Layer w20: R60.1@940,828.5 R59.2@1010,828.5 C41.2@1080,828.5 U6.2@1080,764.13
NetC44_1: C44.1 R63.1 U7.3 | length 143.8
  Top Layer w16: U7.3@937.4,1885.87 937.4,1834.09 C44.1@951.5,1820 1023.2,1820 R63.1@1023.5,1820.31
NetC45_1: C45.1 J8.1 J9.2 R64.1 R66.2 | length 961.3
  Top Layer w12: R64.1@800,2140 R64.1@810,2150
  Top Layer w16: J9.2@720,2650 774.61,2650 844.61,2580 J8.1@990,2580 990,2470 930,2410 850,2410 810,2370 C45.1@810,2210 ; R64.1@801.5,2140 860,2140 R66.2@880,2120 ; R64.1@810,2150 C45.1@810,2220
NetC47_1: C47.1 R65.1 | length 84.1
  Top Layer w16: C47.1@800,2060 870,2060 R65.1@880,2050
NetC47_2: C47.2 R64.2 U7.1 | length 361
  Top Layer w16: R64.2@738.5,2140 720,2121.5 720,1960 794.13,1885.87 U7.1@862.6,1885.87
NetC48_2: C48.2 JP4.2 R68.1 U8.15 U8.16 | length 2172.3
  Top Layer w12: C48.2@2720,2413.07 2726.93,2420 2731.16,2420 2856,2420 2880,2396 2880,2310 2855,2285 R68.1@2791.5,2285
  Top Layer w40: C48.2@2731.16,2420 3036.16,2725 3770,2725 3930,2565 3930,2255 JP4.2@3850,2175
NetC49_1: C49.1 R69.1 | length 88
  Top Layer w20: R69.1@2308.5,2430 2308.5,2393.58 C49.1@2345,2357.09
NetC50_2: C50.2 U8.14 | length 92.9
  Top Layer w12: U8.14@2641.54,2365.59 2714.3,2365.59 C50.2@2728.5,2351.38
NetC55_1: C55.1 JP6.3 R91.1 R196.1 Y1.4 | length 733.6
  Top Layer w10: Y1.4@2873.19,1113.01 2880.01,1119.83 2880.01,1143.47 2891.24,1154.7 C55.1@3011.42,1154.7 3012.4,1154.7 3038.32,1128.79 3038.32,1114.26 v1(3042.91,1109.67) 3038.32,1105.08 3038.32,1088.57 3015.71,1065.96 R196.1@3014.72,1065.96
  Top Layer w12: v1(2893.97,982.32) 2893.97,927.06 2911.78,909.25 2911.78,878.6 2924.48,865.89 R91.1@2925.47,865.89 2925.47,828.96 2905.58,809.07 JP6.3@2905.58,756.19
  Bottom Layer w12: v1(2893.97,982.32) 2898.18,986.53 2919.78,986.53 v1(3042.91,1109.67)
NetC57_1: C57.1 U9.6 | length 170.1
  Top Layer w12: C57.1@3176.57,2098.5 3288.74,2098.5 3292.59,2102.36 3344.45,2102.36 U9.6@3344.88,2102.8
NetC60_2: C60.2 C63.2 R43.1 R48.2 | length 257.6
  Top Layer w25: R48.2@1146.5,1460 C60.2@1240,1460 ; C63.2@1240,1381.5 C60.2@1240,1460 ; R43.1@1325.55,1460 C60.2@1240,1460
NetC127_2: C127.2 R88.1 R101.2 | length 560.4
  Top Layer w12: R101.2@2729.84,909.72 2729.84,959.07 C127.2@2748.16,977.39
  Top Layer w16: C127.2@2748.16,977.39 2748.16,1061.19 v1(2895,1208.03) ; R88.1@2841.51,1350 v1@2893.18,1350
  Bottom Layer w16: v1@2893.67,1206.7 v1(2895,1208.03) v1(2895,1348.18)
NetD3_1: D3.1 R70.1 | length 72.2
  Top Layer w20: D3.1@4000,2079.92 R70.1@4000,2152.17
NetJ1_6: J1.6 R32.2 | length 3649.1
  Top Layer w10: R32.2@1521.5,1020 1533.39,1008.1 v2(1574.41,1008.1) ; v1(4225.53,1661.8) 4230.03,1657.3 4457.5,1657.3 J1.6@4458.5,1656.3
  Bottom Layer w10: v2(1574.41,1008.1) 2012.09,1008.1 2280.28,1276.3 2470.87,1276.3 2564.57,1370 2698.11,1370 2793.59,1465.48 2793.59,1472.15 2793.27,1472.47 2793.27,1745.71 2902.56,1855 4219.26,1855 4225.53,1848.73 v1(4225.53,1661.8)
NetJ1_8: J1.8 R47.2 | length 3765.3
  Top Layer w10: R47.2@1521.5,1090 1535.2,1076.3 1552.59,1076.3 1566.89,1062 v2(1573.39,1062) ; v1(4223.58,1606.5) 4253.69,1636.6 J1.8@4458.5,1636.6
  Bottom Layer w10: v2(1573.39,1062) 2040.71,1062 2273.71,1295 2464.29,1295 2557.16,1387.87 2690.7,1387.87 2775.4,1472.57 2775.4,1758.27 2890,1872.87 4237.65,1872.87 4255.4,1855.12 4255.4,1638.32 v1(4223.58,1606.5)
NetJ1_12: J1.12 R67.2 | length 3793.9
  Top Layer w10: R67.2@1521.5,1150 1522.48,1150 1555.05,1117.43 1568.79,1117.43 v2(1573.39,1112.84) ; v1(4346.56,1587.81) 4353.05,1587.81 4362.44,1597.2 J1.12@4458.5,1597.2
  Bottom Layer w10: v2(1573.39,1112.84) 1574.51,1113.97 2067.39,1113.97 2267.13,1313.7 2457.71,1313.7 2549.76,1405.75 2682.27,1405.75 2757.52,1481 2757.52,1765.68 2882.6,1890.75 4363.87,1890.75 4389.52,1865.1 4389.52,1630.77 v1(4346.56,1587.81)
NetJ1_38: J1.38 R96.2 | length 124.4
  Top Layer w10: R96.2@4393.94,1263.33 4396.44,1265.84 4396.44,1312.92 4423.62,1340.1 4457.5,1340.1 J1.38@4458.5,1341.1
NetJ1_59: J1.59 R21.1
NetJ3_1: J3.1 J4.1 J6.1 R97.2 R98.2 | length 688.2
  Top Layer w25: J3.1@385,740 385,908.19 397.52,920.71 R98.2@398.5,920.71 ; R97.2@703.5,920.71 704.25,919.96 704.25,740.75 J6.1@705,740
  Bottom Layer w25: J3.1@385,740 J4.1@545,740 J6.1@705,740
NetJ5_1: J5.1 R45.2 R58.2 | length 683.5
  Top Layer w16: J5.1@827.2,160 827.2,291.08 934.83,398.7 977.2,398.7 R45.2@998.5,420 978.98,439.53 930.47,439.53 900,470 R58.2@900,678.5
NetJ5_3: J5.3 R23.2 R36.2 | length 949.3
  Top Layer w16: J5.3@1102.8,160 1105.59,162.8 1105.59,310.59 1155,360 1488.5,360 R23.2@1548.5,420 1450,518.5 R36.2@1450,688.5
NetJ7_1: J7.1 R61.2 | length 164.2
  Top Layer w30: R61.2@1671.5,220 1764.41,220 1791.61,192.8 J7.1@1791.61,160
NetJ7_3: J7.3 R62.1 | length 162.1
  Top Layer w30: J7.3@2067.2,160 2067.2,187.2 2100,220 R62.1@2188.5,220
NetJ10_2: J10.2 R76.2 | length 439.5
  Top Layer w20: J10.2@1382,2610 1382,2409.5 1501.5,2290 R76.2@1501.5,2220
NetJ11_2: J11.2 R79.2 | length 521.4
  Top Layer w20: J11.2@1802,2610 1802,2498 1820,2480 1931.5,2480 1961.5,2450 R79.2@1961.5,2220
NetJ13_2: J13.2 R77.1 | length 133.2
  Top Layer w20: J13.2@3378,190 3507.03,190 R77.1@3510,192.97
NetJ14_1: J14.1 R129.1 R197.2 R198.1 | length 647.3
  Top Layer w16: J14.1@2850,370 2850,535 3008.91,693.91 R198.1@3008.91,803.42 ; R198.1@3009.54,803.42 R129.1@3009.54,869.66 3010.53,869.66 3021.23,880.36 3021.23,909.72 3046.22,934.72 R197.2@3046.22,935.7
NetJP2_2: JP2.2 R68.2 U8.13 | length 365.6
  Top Layer w10: U8.13@2641.54,2340 2680,2340 2690,2330 2690,2292.97 2697.97,2285 R68.2@2728.5,2285 2727.44,2283.94 2727.44,2197.66 2784.71,2140.38 JP2.2@2784.71,2075
NetJP6_2: JP6.2 R91.2 Y1.1 | length 339.5
  Top Layer w12: JP6.2@2805.58,756.19 2805.58,811.17 2821.32,826.91 2822.51,826.91 2861.49,865.89 R91.2@2862.47,865.89 2862.47,1043.76 2878.85,1060.13 Y1.1@2878.85,1064.07
NetJP7_1: JP7.1 R87.1 R100.1 R197.1 | length 630.1
  Top Layer w12: R100.1@2965.65,933.89 2965.65,934.88 3000.87,970.1 3018.61,970.1 3033.52,985.01 3046.22,997.71 3051.62,992.31 R87.1@3228.5,992.31 3229.49,992.31 3379.49,842.31 JP7.1@3379.49,717.4
NetJP7_2: JP7.2 R101.1 | length 967.1
  Top Layer w16: R101.1@2791.5,915 2792.12,914.38 2792.12,859.54 v1(2792.74,858.92) v1@2792.79,858.97
  Bottom Layer w12: v1(2792.74,858.92) v1@2796.95,854.71
  Bottom Layer w16: v1(2792.74,858.92) 2792.74,838.24 2817.21,813.77 3121.3,813.77 3332.82,602.25 3452.49,602.25 3479.49,629.25 JP7.2@3479.49,717.4
NetR6_2: R6.2 U1.3 | length 106.6
  Top Layer w16: U1.3@2380.75,682.64 2381.78,681.61 2381.78,652.46 2417.95,616.28 R6.2@2417.95,591.5
NetR8_1: R8.1 R9.1 U3.9 | length 959.9
  Top Layer w8: U3.9@2645.75,1434.88 2645.75,1351.15 2717.58,1279.32 3115.41,1279.32 3165,1328.91 3165,1497.19 3177.81,1510 R8.1@3228.5,1510
  Top Layer w12: R8.1@3228.5,1510 R9.1@3228.5,1579.57
NetR10_1: R10.1 U3.8 | length 861.9
  Top Layer w8: U3.8@2630,1434.88 2630,1344.5 2712.21,1262.29 3124.43,1262.29 3179.25,1317.11 3179.25,1428.98 3189.87,1439.6 R10.1@3228.5,1439.6
NetR12_1: R12.1 U3.10 | length 985.1
  Top Layer w8: U3.10@2661.5,1434.88 2661.5,1361.02 2725.86,1296.66 3102.69,1296.66 3148.83,1342.8 3148.83,1633.76 3166.97,1651.9 R12.1@3228.5,1651.9
NetR13_1: R13.1 R20.1 U3.7 | length 844.2
  Top Layer w8: U3.7@2614.25,1434.88 2614.25,1331.8 2698.84,1247.21 3139.15,1247.21 3191.93,1300 R20.1@3228.5,1300
  Top Layer w12: R20.1@3228.5,1300 R13.1@3228.5,1370
NetR14_1: R14.1 U3.11 | length 1005.8
  Top Layer w8: U3.11@2685.12,1458.5 2685.12,1365.79 2737.21,1313.7 3082.76,1313.7 3132.32,1363.27 3132.32,1668.18 3187.19,1723.04 R14.1@3228.5,1723.04
NetR16_1: R16.1 R130.1 U3.16 | length 669.7
  Top Layer w10: U3.16@2661.5,1545.12 2688.3,1545.12 2933.18,1790 3225.55,1790 R16.1@3228.5,1792.95
NetR18_1: R18.1 R19.1 U3.6 | length 847.2
  Top Layer w8: U3.6@2598.5,1434.88 2598.5,1325.12 2692.48,1231.14 R18.1@3227.01,1231.14
  Top Layer w12: R19.1@3227.01,1161.14 R18.1@3227.01,1231.14
NetR24_2: R24.2 R25.1 U4.4 | length 193.9
  Top Layer w16: R24.2@1548.5,490 R25.1@1548.5,560 1548.5,628.5 1575.87,655.87 U4.4@1592.6,655.87
NetR46_2: R46.2 R49.1 U6.4 | length 198.9
  Top Layer w16: R46.2@998.5,490 R49.1@998.5,560 998.5,637.01 1017.36,655.87 U6.4@1042.6,655.87
NetR65_2: R65.2 R66.1 U7.4 | length 127.6
  Top Layer w12: R65.2@937.4,2047.4 R65.2@940,2050 ; R66.1@940,2120 R66.1@941.5,2118.5
  Top Layer w16: U7.4@937.4,1994.13 R65.2@937.4,2047.4 ; R65.2@941.5,2050 R66.1@941.5,2118.5
NetR72_1: R72.1 U8.6 | length 272.1
  Top Layer w10: R72.1@2310,2101.5 2310,2139.69 2354.05,2183.74 2423.84,2183.74 2488.57,2248.46 U8.6@2498.82,2248.46
NetR73_1: R73.1 U8.8 | length 276.7
  Top Layer w10: R73.1@2380,2101.5 2380,2146.29 2398.71,2165 2433.82,2165 2469.27,2200.45 2535.45,2200.45 2550,2215 U8.8@2550,2248.46
NetR75_1: R75.1 U8.9 | length 239.7
  Top Layer w10: R75.1@2450,2101.5 2450,2143.21 2486.79,2180 2556.26,2180 2575.59,2199.33 U8.9@2575.59,2248.46
NetR78_1: R78.1 U8.10 | length 201.1
  Top Layer w10: R78.1@2520,2101.5 2520,2140 2540,2160 2575,2160 2601.18,2186.18 U8.10@2601.18,2248.46
NetR82_1: R82.1 U8.11 | length 208.7
  Top Layer w10: R82.1@2590,2101.5 2590,2142.45 2641.54,2193.99 U8.11@2641.54,2288.82
NetR83_1: R83.1 U8.12 | length 237.1
  Top Layer w10: U8.12@2641.54,2314.41 2655.59,2314.41 2670,2300 2670,2152.45 2660,2142.45 R83.1@2660,2101.5
NetR89_2: R89.2 R90.1 U1.5 | length 153.6
  Top Layer w16: U1.5@2406.34,857.84 2485.67,857.84 R90.1@2490,853.5 R89.2@2490,785.39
